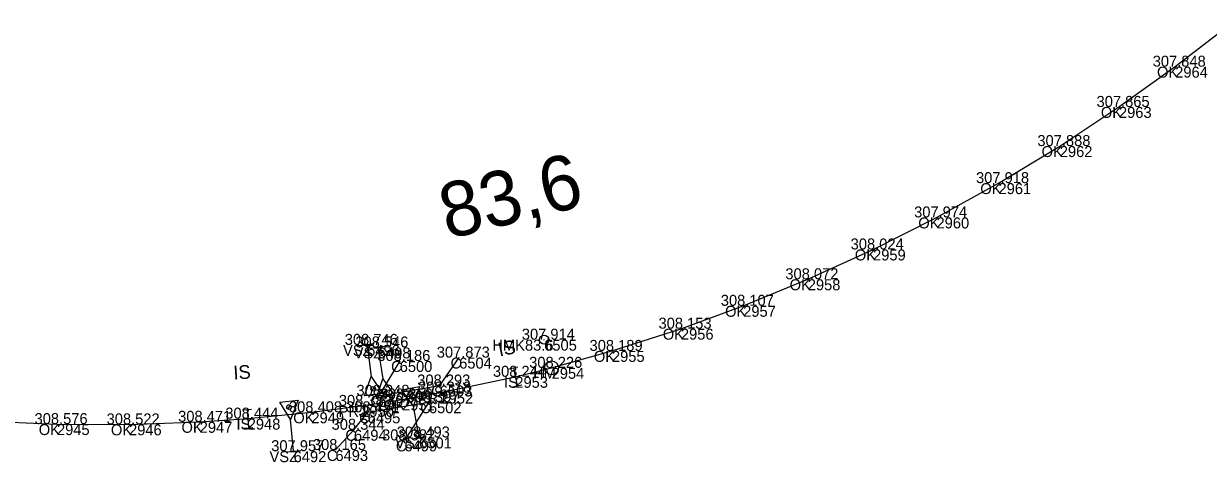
# Model space of a CAD drawing. Extents: x -621782 to -610392, y -1141853 to -1122321.
# Drawn here: x -613643.4 to -613513.9, y -1133199.9 to -1133152 of the extents above; entities that cross this region are included whole.
import ezdxf

# ---------------------------------------------------------------- set-up
doc = ezdxf.new("R2010")
doc.units = 0
for name, color, linetype in [('Vrstva 1', 7, 'Continuous'), ('Vrstva 3', 7, 'Continuous'), ('Vrstva 4', 7, 'Continuous'), ('Vrstva 51', 7, 'Continuous'), ('Vrstva 60', 7, 'Continuous'), ('Vrstva 61', 7, 'Continuous'), ('Vrstva 62', 7, 'Continuous'), ('Vrstva 7', 7, 'Continuous')]:
    doc.layers.add(name, color=color, linetype=linetype)

msp = doc.modelspace()

# ---------------------------------------------------------------- linework, layer by layer
at = {"layer": 'Vrstva 1'}
msp.add_lwpolyline([(-613648.2, -1133195.4), (-613639.79, -1133195.77), (-613631.91, -1133195.8), (-613624.18, -1133195.52), (-613618.93, -1133195.17), (-613611.97, -1133194.48), (-613606.52, -1133193.78), (-613602.05, -1133193.08), (-613597.85, -1133192.33), (-613589.67, -1133190.6), (-613585.7, -1133189.62), (-613579.1, -1133187.77), (-613571.56, -1133185.34), (-613564.75, -1133182.84), (-613557.69, -1133179.94), (-613550.55, -1133176.68), (-613543.61, -1133173.18), (-613536.83, -1133169.43), (-613530.13, -1133165.38), (-613523.66, -1133161.1), (-613517.51, -1133156.7), (-613511.4, -1133152)], dxfattribs=at)
at = {"layer": 'Vrstva 3'}
for p, q in [((-613590.37, -1133189.72), (-613589.39, -1133189.51)), ((-613589.88, -1133189.62), (-613589.46, -1133191.57)), ((-613589.95, -1133191.68), (-613588.97, -1133191.47)), ((-613619.49, -1133194.2), (-613618.5, -1133194.13)), ((-613618.99, -1133194.17), (-613618.86, -1133196.16)), ((-613619.36, -1133196.2), (-613618.36, -1133196.13))]:
    msp.add_line(p, q, dxfattribs=at)
at = {"layer": 'Vrstva 4'}
for p, q in [((-613605.1, -1133187.01), (-613606.64, -1133187.21)), ((-613603.93, -1133187.27), (-613605.47, -1133187.51)), ((-613605.07, -1133191.71), (-613605.37, -1133192.1)), ((-613603.79, -1133191.97), (-613604.08, -1133192.37)), ((-613601.2, -1133192.67), (-613600.92, -1133192.27)), ((-613614.56, -1133194.1), (-613614.25, -1133193.72)), ((-613600.94, -1133197.37), (-613599.41, -1133197.1)), ((-613614.68, -1133198.8), (-613613.13, -1133198.66))]:
    msp.add_line(p, q, dxfattribs=at)
for points in [[(-613605.87, -1133187.11), (-613605.43, -1133190.56), (-613604.19, -1133192.42), (-613606.17, -1133192.68), (-613605.43, -1133190.56)], [(-613604.7, -1133187.39), (-613604.17, -1133190.83), (-613602.89, -1133192.66), (-613604.87, -1133192.97), (-613604.17, -1133190.83)], [(-613600.18, -1133197.23), (-613600.79, -1133193.81), (-613602.11, -1133192.01), (-613600.14, -1133191.65), (-613600.79, -1133193.81)], [(-613613.91, -1133198.73), (-613614.25, -1133195.27), (-613615.42, -1133193.37), (-613613.43, -1133193.17), (-613614.25, -1133195.27)], [(-613606.52, -1133193.78), (-613602.05, -1133193.08), (-613597.85, -1133192.33)]]:
    msp.add_lwpolyline(points, dxfattribs=at)
for centre in [(-613605.22, -1133191.91), (-613603.94, -1133192.17), (-613601.06, -1133192.47), (-613614.41, -1133193.91)]:
    msp.add_circle(centre, 0.248, dxfattribs=at)
at = {"layer": 'Vrstva 51'}
for points in [[(-613602.31, -1133188.87), (-613604.59, -1133192.68), (-613597.94, -1133191.55), (-613595.81, -1133188.5)], [(-613609.34, -1133198.6), (-613607.31, -1133196.39), (-613605.81, -1133194.48), (-613599.12, -1133193.38), (-613601.79, -1133197.55)]]:
    msp.add_lwpolyline(points, dxfattribs=at)
at = {"layer": 'Vrstva 60'}
for p, q in [((-613517.51, -1133156.7), (-613517.51, -1133156.7)), ((-613523.66, -1133161.1), (-613523.66, -1133161.1)), ((-613530.13, -1133165.38), (-613530.13, -1133165.38)), ((-613536.83, -1133169.43), (-613536.83, -1133169.43)), ((-613543.61, -1133173.18), (-613543.61, -1133173.18)), ((-613550.55, -1133176.68), (-613550.55, -1133176.68)), ((-613557.69, -1133179.94), (-613557.69, -1133179.94)), ((-613564.75, -1133182.84), (-613564.75, -1133182.84)), ((-613571.56, -1133185.34), (-613571.56, -1133185.34)), ((-613586.51, -1133186.54), (-613586.51, -1133186.54)), ((-613605.87, -1133187.11), (-613605.87, -1133187.11)), ((-613604.7, -1133187.39), (-613604.7, -1133187.39)), ((-613579.1, -1133187.77), (-613579.1, -1133187.77)), ((-613602.31, -1133188.87), (-613602.31, -1133188.87)), ((-613595.81, -1133188.5), (-613595.81, -1133188.5)), ((-613589.67, -1133190.6), (-613589.67, -1133190.6)), ((-613585.7, -1133189.62), (-613585.7, -1133189.62)), ((-613597.94, -1133191.55), (-613597.94, -1133191.55)), ((-613604.59, -1133192.68), (-613604.59, -1133192.68)), ((-613602.05, -1133193.08), (-613602.05, -1133193.08)), ((-613597.85, -1133192.33), (-613597.85, -1133192.33)), ((-613611.97, -1133194.48), (-613611.97, -1133194.48)), ((-613606.52, -1133193.78), (-613606.52, -1133193.78)), ((-613605.81, -1133194.48), (-613605.81, -1133194.48)), ((-613599.12, -1133193.38), (-613599.12, -1133193.38)), ((-613639.79, -1133195.77), (-613639.79, -1133195.77)), ((-613631.91, -1133195.8), (-613631.91, -1133195.8)), ((-613624.18, -1133195.52), (-613624.18, -1133195.52)), ((-613618.93, -1133195.17), (-613618.93, -1133195.17)), ((-613607.31, -1133196.39), (-613607.31, -1133196.39)), ((-613601.79, -1133197.55), (-613601.79, -1133197.55)), ((-613600.18, -1133197.23), (-613600.18, -1133197.23)), ((-613613.91, -1133198.73), (-613613.91, -1133198.73)), ((-613609.34, -1133198.6), (-613609.34, -1133198.6))]:
    msp.add_line(p, q, dxfattribs=at)
at = {"layer": 'Vrstva 7'}
msp.add_line((-613586.56, -1133186.55), (-613586.47, -1133186.52), dxfattribs=at)
for centre, radius in [((-613586.51, -1133186.54), 0.5), ((-613585.7, -1133189.62), 0.75)]:
    msp.add_circle(centre, radius, dxfattribs=at)

# ---------------------------------------------------------------- texts
at = {"layer": 'Vrstva 3'}
for rotation, p in [(11.966, (-613591.38, -1133188.39)), (3.8763, (-613620.45, -1133190.91))]:
    msp.add_text('IS', height=1.5, rotation=rotation, dxfattribs=at).set_placement(p)
at = {"layer": 'Vrstva 60'}
for s, p in [('2964', (-613517.51, -1133157.9)), ('2963', (-613523.66, -1133162.3)), ('2962', (-613530.13, -1133166.58)), ('2961', (-613536.83, -1133170.63)), ('2960', (-613543.61, -1133174.38)), ('2959', (-613550.55, -1133177.88)), ('2958', (-613557.69, -1133181.14)), ('2957', (-613564.75, -1133184.04)), ('2956', (-613571.56, -1133186.54)), ('6505', (-613586.51, -1133187.74)), ('6496', (-613605.87, -1133188.31)), ('6498', (-613604.7, -1133188.59)), ('2955', (-613579.1, -1133188.97)), ('6500', (-613602.31, -1133190.07)), ('6504', (-613595.81, -1133189.7)), ('2953', (-613589.67, -1133191.8)), ('2954', (-613585.7, -1133190.82)), ('6503', (-613597.94, -1133192.75)), ('6497', (-613604.59, -1133193.88)), ('2951', (-613602.05, -1133194.28)), ('2952', (-613597.85, -1133193.53)), ('2949', (-613611.97, -1133195.68)), ('2950', (-613606.52, -1133194.98)), ('6495', (-613605.81, -1133195.68)), ('6502', (-613599.12, -1133194.58)), ('2945', (-613639.79, -1133196.97)), ('2946', (-613631.91, -1133197)), ('2947', (-613624.18, -1133196.72)), ('2948', (-613618.93, -1133196.37)), ('6494', (-613607.31, -1133197.59)), ('6499', (-613601.79, -1133198.75)), ('6501', (-613600.18, -1133198.43)), ('6492', (-613613.91, -1133199.93)), ('6493', (-613609.34, -1133199.8))]:
    msp.add_text(s, height=1.2, dxfattribs=at).set_placement(p)
at = {"layer": 'Vrstva 61'}
for s, p in [('307.848', (-613519.97, -1133156.7)), ('307.865', (-613526.11, -1133161.1)), ('307.888', (-613532.58, -1133165.38)), ('307.918', (-613539.29, -1133169.43)), ('307.974', (-613546.06, -1133173.18)), ('308.024', (-613553, -1133176.68)), ('308.072', (-613560.14, -1133179.94)), ('308.107', (-613567.2, -1133182.84)), ('308.153', (-613574.01, -1133185.34)), ('307.914', (-613588.96, -1133186.54)), ('308.746', (-613608.32, -1133187.11)), ('308.546', (-613607.16, -1133187.39)), ('308.189', (-613581.55, -1133187.77)), ('308.186', (-613604.76, -1133188.87)), ('307.873', (-613598.26, -1133188.5)), ('308.226', (-613588.15, -1133189.62)), ('308.293', (-613600.39, -1133191.55)), ('308.244', (-613592.12, -1133190.6)), ('308.348', (-613607.04, -1133192.68)), ('308.356', (-613604.51, -1133193.08)), ('308.318', (-613600.3, -1133192.33)), ('308.383', (-613608.97, -1133193.78)), ('308.397', (-613601.57, -1133193.38)), ('308.471', (-613626.54, -1133195.52)), ('308.444', (-613621.38, -1133195.17)), ('308.408', (-613614.42, -1133194.48)), ('308.451', (-613608.17, -1133194.48)), ('308.576', (-613642.24, -1133195.77)), ('308.522', (-613634.36, -1133195.8)), ('308.344', (-613609.76, -1133196.39)), ('308.382', (-613604.24, -1133197.55)), ('308.493', (-613602.63, -1133197.23)), ('307.957', (-613616.36, -1133198.73)), ('308.165', (-613611.8, -1133198.6))]:
    msp.add_text(s, height=1.2, dxfattribs=at).set_placement(p)
at = {"layer": 'Vrstva 62'}
for s, p in [('OK', (-613519.5, -1133157.9)), ('OK', (-613525.64, -1133162.3)), ('OK', (-613532.12, -1133166.58)), ('OK', (-613538.82, -1133170.63)), ('OK', (-613545.6, -1133174.38)), ('OK', (-613552.54, -1133177.88)), ('OK', (-613559.67, -1133181.14)), ('OK', (-613566.73, -1133184.04)), ('OK', (-613573.54, -1133186.54)), ('HMK83.6', (-613592.18, -1133187.74)), ('VSZ', (-613608.51, -1133188.31)), ('VSZ', (-613607.34, -1133188.59)), ('OK', (-613581.08, -1133188.97)), ('C', (-613603.25, -1133190.07)), ('C', (-613596.75, -1133189.7)), ('IS', (-613590.9, -1133191.8)), ('HM', (-613587.73, -1133190.82)), ('C', (-613598.87, -1133192.75)), ('C', (-613605.52, -1133193.88)), ('OK', (-613604.04, -1133194.28)), ('PRJ', (-613600.33, -1133193.53)), ('OK', (-613613.95, -1133195.68)), ('PRJ', (-613609, -1133194.98)), ('C', (-613606.75, -1133195.68)), ('C', (-613600.06, -1133194.58)), ('OK', (-613641.78, -1133196.97)), ('OK', (-613633.89, -1133197)), ('OK', (-613626.17, -1133196.72)), ('IS', (-613620.16, -1133196.37)), ('C', (-613608.25, -1133197.59)), ('VSZ', (-613602.82, -1133198.43)), ('C', (-613602.73, -1133198.75)), ('VSZ', (-613616.55, -1133199.93)), ('C', (-613610.28, -1133199.8))]:
    msp.add_text(s, height=1.2, dxfattribs=at).set_placement(p)
at = {"layer": 'Vrstva 7'}
msp.add_text('83,6', height=6, rotation=13.863, dxfattribs=at).set_placement((-613597.09, -1133175.59))

doc.saveas('drawing.dxf')
